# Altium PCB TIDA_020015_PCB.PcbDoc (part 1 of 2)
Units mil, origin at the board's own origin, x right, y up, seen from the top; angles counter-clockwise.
Board outline 1470 x 1510 mil, 2 copper layers (Top Layer, Bottom Layer), stack 62 mil thick; 90 components, 41 nets, 222 pads, 53 vias.
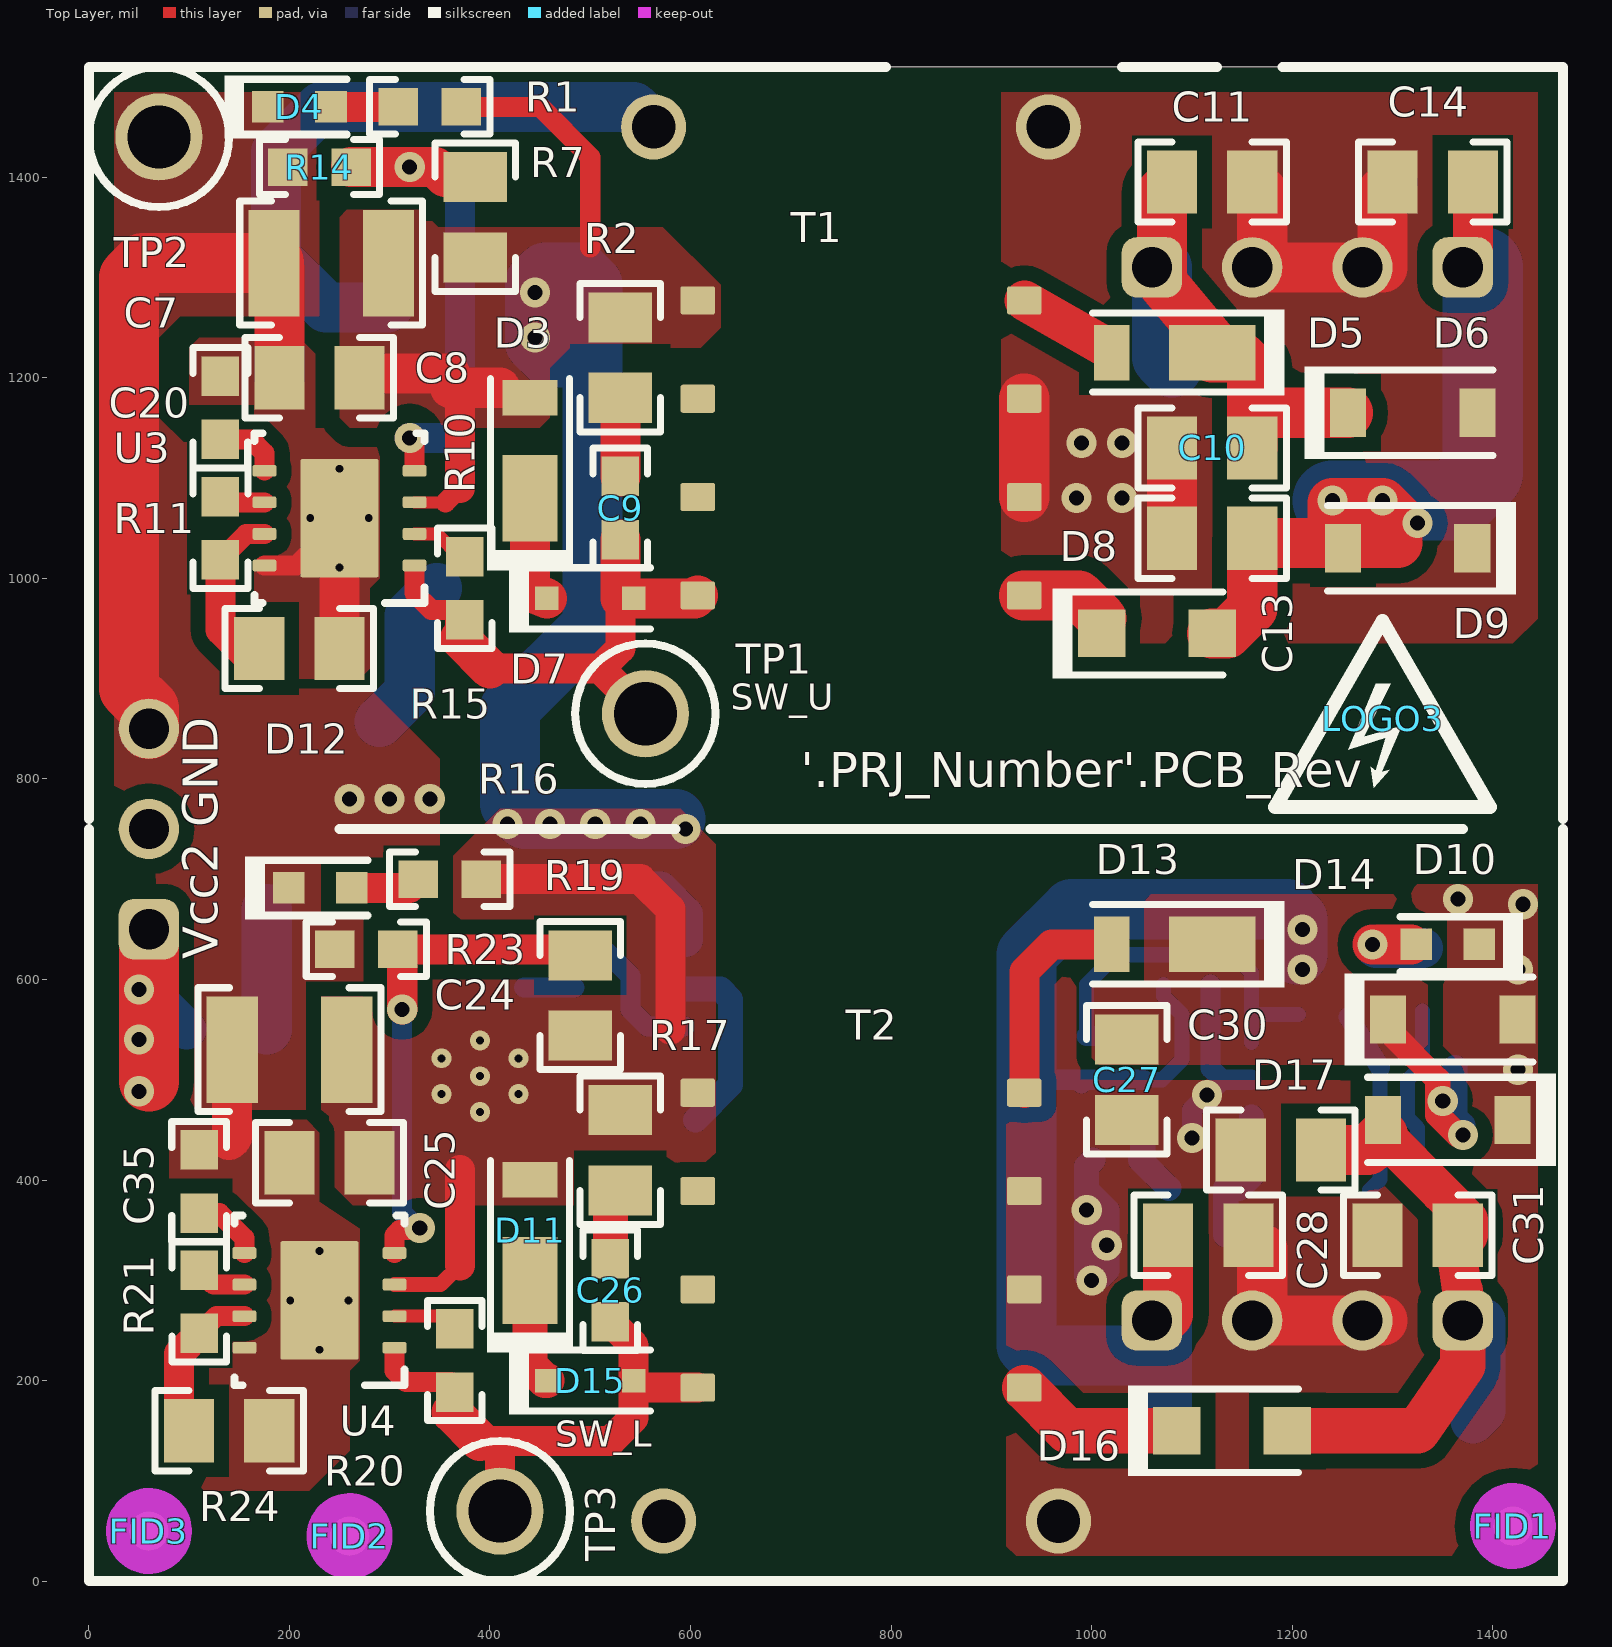
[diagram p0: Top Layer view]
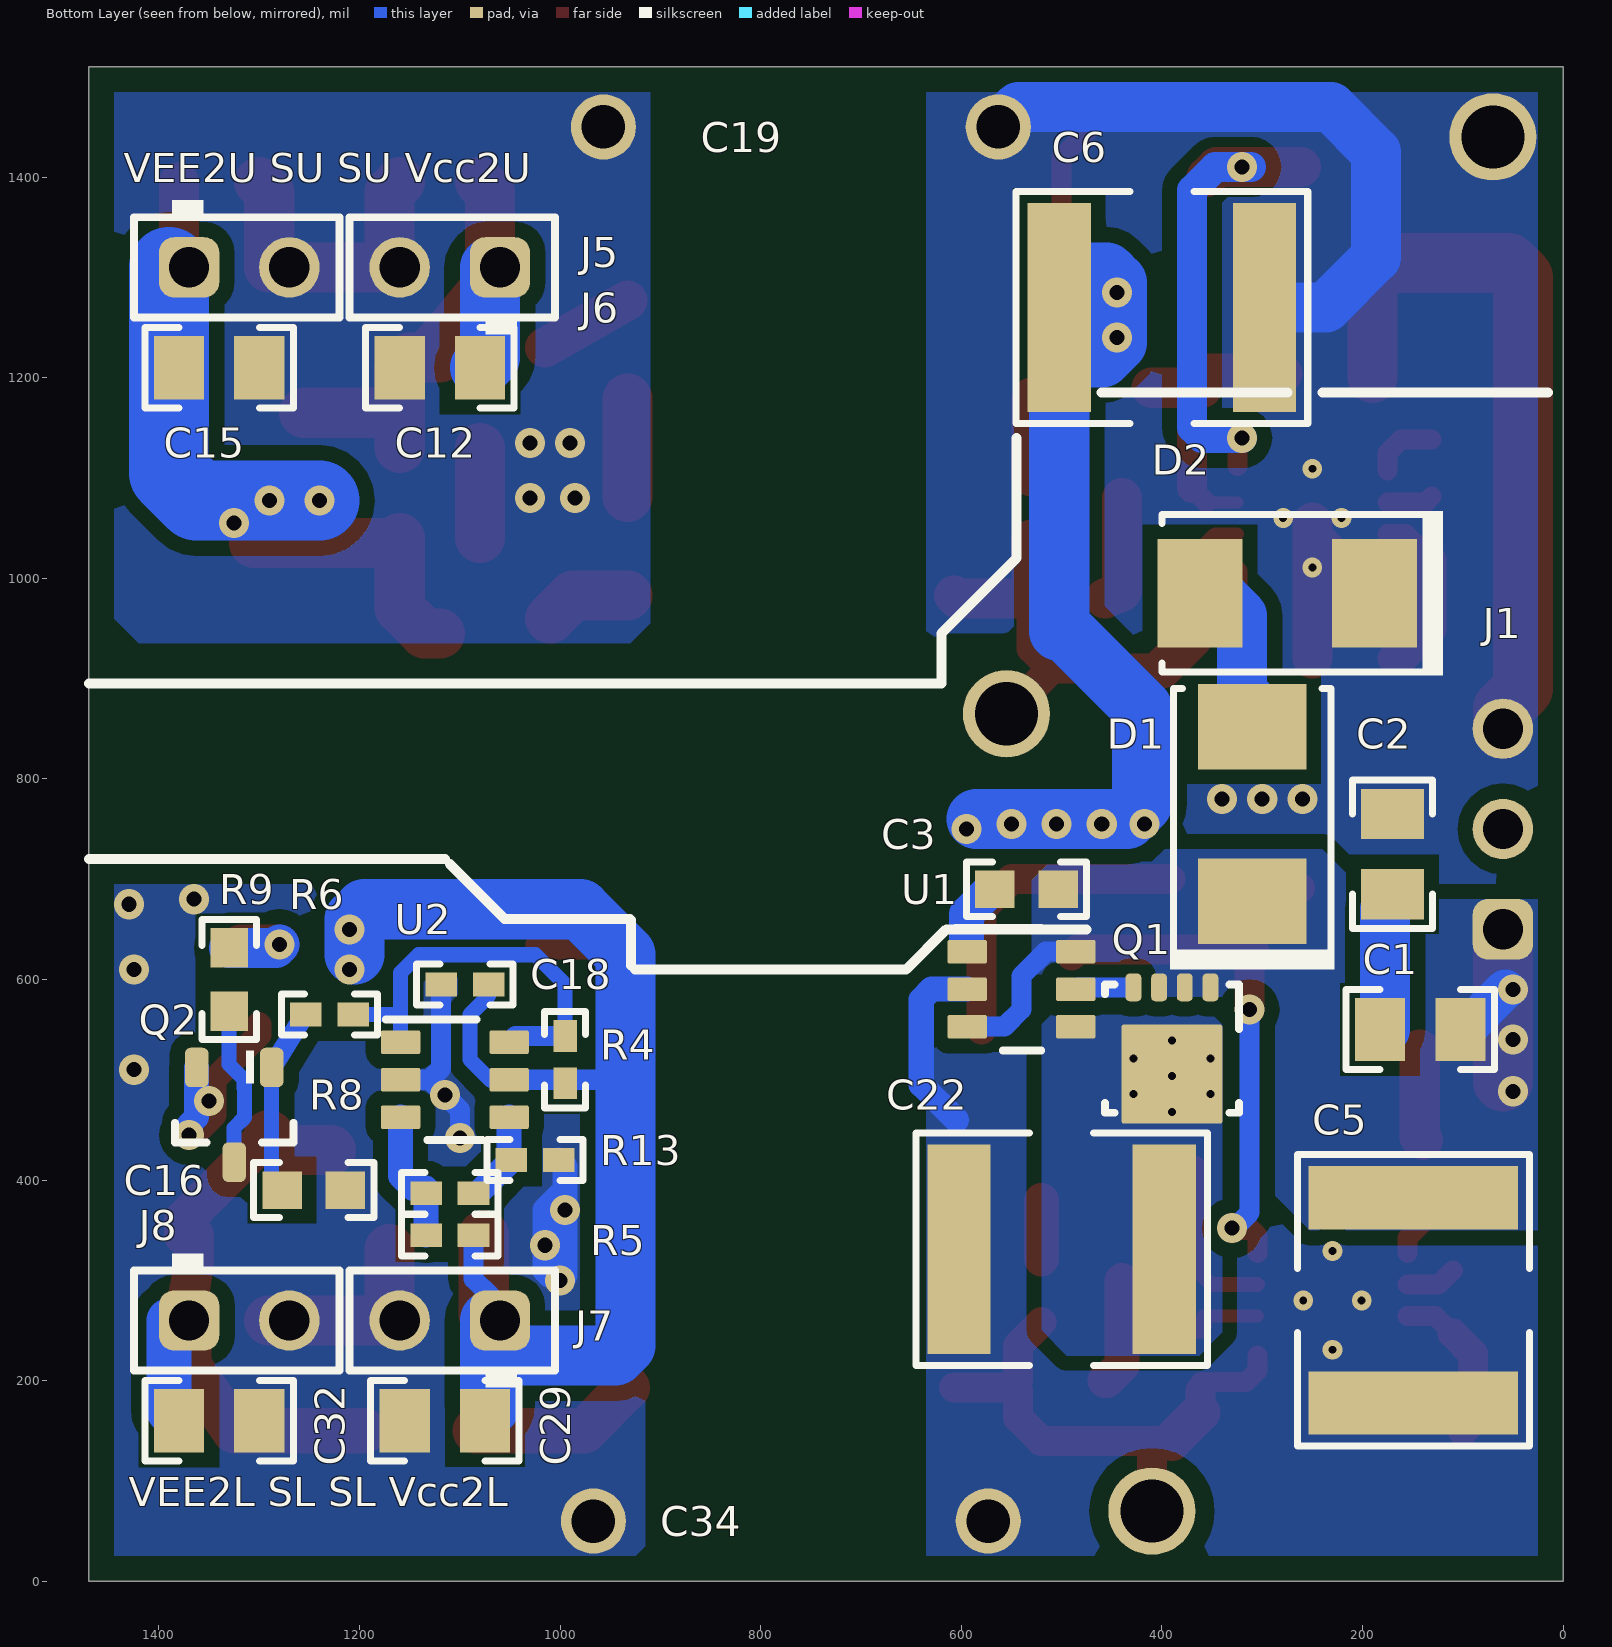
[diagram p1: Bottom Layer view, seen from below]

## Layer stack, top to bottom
Top Solder: solder mask 0.4, Solder Resist, Dk 3.5
Top Layer: signal copper 1.4
Dielectric1: core 59.2, FR-4, Dk 4.8
Bottom Layer: signal copper 1.4
Bottom Solder: solder mask 0.4, Solder Resist, Dk 3.5

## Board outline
0,0 1470,0 1470,1510 0,1510

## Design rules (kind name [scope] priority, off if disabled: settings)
AcuteAngle [All] p1: minimum=4.50000000000000E+0001 checktracksonly=FALSE
AssemblyTestPointUsage [All] p1: valid=2
BoardOutlineClearance BoardOutlineClearance_MountingHoles [OnCopper and InComponentClass('Mounting Holes')] p1: gap=40 ignorepadtopadclearanceinfootprint=FALSE
BoardOutlineClearance BoardOutlineClearance_Poly [OnCopper and IsPoly] p2: gap=25 ignorepadtopadclearanceinfootprint=FALSE
BoardOutlineClearance [OnCopper and Not InComponentClass('Logo') and not InComponentClass('FiducialMark') and not InRegion(1000,500,4000,800) and not InPoly] p3: gap=10 ignorepadtopadclearanceinfootprint=FALSE
Clearance Clearance_SW [InNet('SW_L')or InNet('SW_U')] p1: gap=19 ignorepadtopadclearanceinfootprint=FALSE
Clearance Clearance_Vin_U1 [InNet('Vin') or InNet('Vin_Pri') vs not InComponent('U1')  Xor  NetQ1_4] p2: gap=19 ignorepadtopadclearanceinfootprint=FALSE
Clearance Clearance_Keepouts [((IsTrack Or IsArc) And Not InPoly) And IsFree and IsKeepOut vs ((IsTrack Or IsArc) And Not InPoly) And IsFree and IsKeepOut] p3: gap=0 ignorepadtopadclearanceinfootprint=FALSE
Clearance Clearance_Poly [InPolygon] p4: gap=15 ignorepadtopadclearanceinfootprint=FALSE
Clearance Clearance_FiducialMark [IsKeepOut and InComponentClass('FiducialMark') vs IsPad and InComponentClass('FiducialMark')] p5: gap=0 ignorepadtopadclearanceinfootprint=FALSE
Clearance [All] p6: gap=7.87 ignorepadtopadclearanceinfootprint=FALSE except(0: Arc-Hole Track-Hole SMDPad-Hole THPad-Hole Via-Hole Fill-Hole Poly-Hole Region-Hole Text-Hole)
ComponentClearance ComponentClearance_MountingHoles_FiducialMarks [InComponentClass('Mounting Holes') vs InComponentClass('FiducialMark')] p1: gap=50 collisioncheckmode=3 verticalgap=10 showdistances=FALSE
ComponentClearance ComponentClearance_Shunt [InComponentClass('Header') vs InComponentClass('Shunt')] p2: gap=0 collisioncheckmode=3 verticalgap=0 showdistances=FALSE
ComponentClearance ComponentClearance_Logo [InComponentClass('Logo')] p3: gap=50 collisioncheckmode=3 verticalgap=10 showdistances=FALSE
ComponentClearance ComponentClearance_ScrewToNut [(HasFootprint('NY PMS 440 0025 PH')) vs (HasFootprint('Keystone_1902C'))] p4: gap=5 collisioncheckmode=3 verticalgap=10 showdistances=FALSE
ComponentClearance ComponentClearance_MountingHoles [InComponentClass('Mounting Holes')] p5: gap=250 collisioncheckmode=3 verticalgap=100000 showdistances=FALSE
ComponentClearance ComponentClearance_SmallPassives [HasFootprint('0201*') or HasFootprint('0402*') or HasFootprint('0508') or HasFootprint('0603*') or HasFootprint('0612') or HasFootprint('0805*') or HasFootprint('0815*') or HasFootprint('0830*') or HasFootprint('1206*') or HasFootprint('1210*') or HasFootprint('1808*') or HasFootprint('1812*') or HasFootprint('1825*') or HasFootprint('2010*') or HasFootprint('2220*') or HasFootprint('2225*') or HasFootprint('2512*') or HasFootprint('2728*') or HasFootprint('3518*') vs HasFootprint('0201*') or HasFootprint('0402*') or HasFootprint('0508') or HasFootprint('0603*') or HasFootprint('0612') or HasFootprint('0805*') or HasFootprint('0815*') or HasFootprint('0830*') or HasFootprint('1206*') or HasFootprint('1210*') or HasFootprint('1808*') or HasFootprint('1812*') or HasFootprint('1825*') or HasFootprint('2010*') or HasFootprint('2220*') or HasFootprint('2225*') or HasFootprint('2512*') or HasFootprint('2728*') or HasFootprint('3518*')] p6: gap=14.96 collisioncheckmode=3 verticalgap=10 showdistances=FALSE
ComponentClearance ComponentClearance_THtoSMT [IsThruComponent vs IsSMTComponent] p7: gap=20 collisioncheckmode=3 verticalgap=20 showdistances=FALSE
ComponentClearance ComponentClearance_THtoTH [IsThruComponent vs IsThruComponent] p8: gap=10 collisioncheckmode=3 verticalgap=20 showdistances=FALSE
ComponentClearance [All] p9: gap=20 collisioncheckmode=3 verticalgap=10 showdistances=FALSE
DiffPairsRouting [All] p1: maxlimit=100 minlimit=10 mostfreqgap=10 toplayer_minwidth=15 toplayer_maxwidth=15 toplayer_prefwidth=15 bottomlayer_minwidth=15 bottomlayer_maxwidth=15 bottomlayer_prefwidth=15 maxuncoupledlength=1000
FabricationTestPointUsage TestPointUsage [All] p1: valid=2 allowmultiple=FALSE
FabricationTestpoint Testpoint [All] p1: side=3 testpointundercomponent=TRUE minsize=40 maxsize=100 preferedsize=60 minholesize=0 maxholesize=40 preferedholesize=32 testpointgrid=1 allowsidetop=TRUE allowsidebottom=TRUE usegrid=TRUE gridtolerance=0.01
FanoutControl Fanout_LCC [IsLCC] p1: bgadir=Out bgaviamode=Centered fanoutstyle=Auto fanoutdirection=Alternating viagrid=1 // Fanout_LCC (Default Rule)
FanoutControl Fanout_BGA [IsBGA] p2: bgadir=Out bgaviamode=Centered fanoutstyle=Auto fanoutdirection=Alternating viagrid=1 // Fanout_BGA (Default Rule)
FanoutControl Fanout_Default [All] p4: bgadir=Out bgaviamode=Centered fanoutstyle=Auto fanoutdirection=Alternating viagrid=1 // Fanout_Default (Default Rule)
FanoutControl Fanout_Small [(CompPinCount < 5)] p5: bgadir=Out bgaviamode=Centered fanoutstyle=Auto fanoutdirection=OutThenIn viagrid=1 // Fanout_Small (Default Rule)
HoleSize [All] p1: absolutevalues=TRUE maxlimit=251 minlimit=7.87 maxpercent=80.000 minpercent=20.000
MinimumAnnularRing MinimumAnnularRing_ThermalPadVias [IsVia and InAnyComponent] p1: minimumring=5.91
MinimumAnnularRing [All] p2: minimumring=7
MinimumSolderMaskSliver MinimumSolderMaskSliver_Logo [InComponentClass('Logo') vs InComponentClass('Logo')] p1: minsoldermaskwidth=0.7
MinimumSolderMaskSliver [All] p2: minsoldermaskwidth=3.94
PlaneClearance [All] p1: clearance=15
PlaneConnect [All] p1: planeconnectstyle=Relief reliefexpansion=10 reliefentries=4 reliefconductorwidth=10 reliefairgap=10
PolygonConnect [All] p1: connectstyle=Direct reliefconductorwidth=10 reliefentries=4 polygonreliefangle="90 Angle" airgapwidth=10
RoutingVias ThermalPadVias [IsVia and InAnyComponent] p1: holewidth=7.87 width=19.68 viastyle="Through Hole" minholewidth=7.87 minwidth=19.68 maxholewidth=12.99 maxwidth=23.62
RoutingVias [All] p2: holewidth=16 width=34 viastyle="Through Hole" minholewidth=7.87 minwidth=26 maxholewidth=40 maxwidth=65
SilkToBoardRegionClearance [Not ((IsComment or IsDesignator) And (Hide <> 'False')) and not InRegion(1000,500,4000,800)] p1:
SilkToSilkClearance SilkToSilkClearance_Pb-FreeLogo [(HasFootprint('Pb-Free_Overlay_Medium') OR HasFootprint('Pb-Free_Overlay_Small')) vs (HasFootprint('Pb-Free_Overlay_Medium') OR HasFootprint('Pb-Free_Overlay_Small'))] p1: silktosilkclearance=0
SilkToSilkClearance [All] p2: silktosilkclearance=0
SilkToSolderMaskClearance SilkToComponentPadClearance [(IsPad or IsFill or IsRegion) and InAnycomponent] p1: minsilkscreentomaskgap=0 clearancetoexposedcopper=TRUE
SilkToSolderMaskClearance "Silk to Solder Mask Opening" [All] p2: minsilkscreentomaskgap=0 clearancetoexposedcopper=FALSE
SolderMaskExpansion [All] p1: expansion=1.97
Width [All] p1: maxlimit=100 minlimit=6 preferedwidth=10 checkconnectedcopper=TRUE
14 further rules are at their usual default settings.

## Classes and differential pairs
component class AssemblyNote: ZZ1 ZZ2 ZZ3
component class FiducialMark: FID1 FID2 FID3
component class TIDA_020015_PSR_Flyback_Hardware: FID1 FID2 FID3 LOGO3 ZZ1 ZZ2 ZZ3
component class Header: J1 J5 J6 J7 J8
component class TIDA-020015_PSR_Flyback: C1 C2 C3 C5 C6 C7 C8 C9 C10 C11 C12 C13 C14 C15 C16 C18 C19 C20 C22 C24 C25 C26 C27 C28 C29 C30 C31 C32 C34 C35 D1 D2 D3 D4 D5 D6 D7 D8 D9 D10 D11 D12 D13 D14 D15 D16 D17 J1 J5 J6 J7 J8 Q1 Q2 R1 R2 R4 R5 R6 R7 R8 R9 R10 R11 R13 R14 R15 R16 R17 R19 R20 R21 R23 R24 T1 T2 TP1 TP2 TP3 U1 U2 U3 U4

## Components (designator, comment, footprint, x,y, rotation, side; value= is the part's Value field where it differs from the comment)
C1 "GRM21BR71H104KA01L" 0805_HV 142.48,550 r0 bottom value=0.1uF
C2 "GRM21BR71H104KA01L" 0805_HV 170,725 r270 bottom value=0.1uF
C3 "GRM188R61H105KAALD" 0603 535,690 r180 bottom value=1uF
C5 "C5750X7S2A106K230KB" 2220_250 149.29,280 r270 bottom value=10uF
C6 "C5750X7S2A106K230KB" 2220_250 400,1270 r180 bottom value=10uF
C7 "GCM32DC72A475KE02L" 1210_220 241.73,1314.3 r180 top value=4.7uF
C8 "GRM21BR72A104KAC4L" 0805_HV 230,1200 r180 top value=0.1uF
C9 "GRM1885C2A221JA01D" 0603 530,1070 r270 top value=220pF
C10 "GRM21BR61E226ME44L" 0805_HV 1120,1130 r180 top value=22uF
C11 "GRM21BR61E226ME44L" 0805_HV 1120,1395 r0 top value=22uF
C12 "GRM21BR71H224KA01L" 0805_HV 1120,1210 r0 bottom value=0.22uF
C13 "GRM21BR61E226ME44L" 0805_HV 1120,1040 r0 top value=22uF
C14 "GRM21BR61E226ME44L" 0805_HV 1340,1395 r0 top value=22uF
C15 "GRM21BR71H224KA01L" 0805_HV 1340,1210 r0 bottom value=0.22uF
C16 "GRM1885C2A101JA01D" 0603 1245.66,390 r180 bottom value=100pF
C18 "Capacitor" 0402 1095,595 r0 bottom value=0.1uF
C19 "S102M59Z5UU83L0R" S102_1500x800x1800 760,1450 r180 bottom value=1000pF
C20 "GRM188R71C473KA01D" 0603 131.3,1170 r90 top value=0.047uF
C22 "C5750X7S2A106K230KB" 2220_250 500,331.02 r0 bottom value=10uF
C24 "GCM32DC72A475KE02L" 1210_220 200,530 r180 top value=4.7uF
C25 "GRM21BR72A104KAC4L" 0805_HV 240,417.24 r180 top value=0.1uF
C26 "GRM1885C2A221JA01D" 0603 520,290 r270 top value=220pF
C27 "GRM21BR61E226ME44L" 0805_HV 1035,500 r270 top value=22uF
C28 "GRM21BR61E226ME44L" 0805_HV 1116.22,345 r0 top value=22uF
C29 "GRM21BR71H224KA01L" 0805_HV 1115,160 r0 bottom value=0.22uF
C30 "GRM21BR61E226ME44L" 0805_HV 1188.66,430 r0 top value=22uF
C31 "GRM21BR61E226ME44L" 0805_HV 1325,345 r0 top value=22uF
C32 "GRM21BR71H224KA01L" 0805_HV 1340,160 r0 bottom value=0.22uF
C34 "S102M59Z5UU83L0R" S102_1500x800x1800 770,60 r180 bottom value=1000pF
C35 "GRM188R71C473KA01D" 0603 110,398.5 r90 top value=0.047uF
D1 "SMBJ26A-13-F" SMB 310,765 r90 bottom value=26V
D2 "SMBJ14A-13-F" SMB 275,985 r0 bottom value=14V
D3 "DFLZ24-7" PowerDI123 440,1130 r90 top value=24V
D4 "150060GS75000" WL-SMCW_GREEN 210,1470 r0 top value=Green
D5 "DFLU1200-7" PowerDI123 1070,1225 r180 top value=200V
D6 "BZT52C18-7-F" SOD-123 1320,1165 r0 top value=18V
D7 "CMDD4448" SOD-323 500,980 r0 top value=75V
D8 "PMEG10010ELRX" SOD-123W 1065,945 r0 top value=100V
D9 "BZT52C8V2-7-F" SOD-123 1315,1030 r180 top value=8.2V
D10 "150060SS75000" WL-SMCW_RED 1355,635 r180 top value="Super Red"
D11 "DFLZ24-7" PowerDI123 440,350 r90 top value=24V
D12 "150060GS75000" WL-SMCW_GREEN 230.75,691.32 r0 top value=Green
D13 "DFLU1200-7" PowerDI123 1070,635 r180 top value=200V
D14 "BZT52C18-7-F" SOD-123 1360,560 r0 top value=18V
D15 "CMDD4448" SOD-323 500,200 r0 top value=75V
D16 "PMEG10010ELRX" SOD-123W 1140,150 r0 top value=100V
D17 "BZT52C8V2-7-F" SOD-123 1355,460 r180 top value=8.2V
FID1 "Fiducial" Fiducial10-20 1420,55 r0 top
FID2 "Fiducial" Fiducial10-20 260,45 r0 top
FID3 "Fiducial" Fiducial10-20 60,50 r0 top
J1 "TSW-103-08-G-S" Samtec_TSW-103-08-x-S 60,750 r90 bottom
J5 "TSW-102-08-G-S" Samtec_TSW-102-08-x-S 1110,1310 r0 bottom
J6 "TSW-102-08-G-S" Samtec_TSW-102-08-x-S 1320,1310 r180 bottom
J7 "TSW-102-08-G-S" Samtec_TSW-102-08-x-S 1110,260 r0 bottom
J8 "TSW-102-08-G-S" Samtec_TSW-102-08-x-S 1320,260 r180 bottom
LOGO3 "DANGER HIGH VOLTAGE" IEC_HighVoltage_Small 1290,860 r0 top
Q1 "CSD18543Q3A" DNH0008A 390,531.02 r270 bottom value=60V
Q2 "BC857C-7-F" SOT-23 1325,465 r270 bottom value="45 V"
R1 "CRCW060310K0FKEA" 0603 340,1470 r0 top value=10.0k
R2 "CRCW0805100RFKEA" 0805_HV 530,1220 r90 top value=100
R4 "CRCW040249K9FKED" 0402 995,520 r90 bottom value=49.9k
R5 "CRCW0402240KFKED" 0402 1110,345 r180 bottom value=240k
R6 "CRCW040210K0FKED" 0402 1230,565 r0 bottom value=10.0k
R7 "CRCW0805100KFKEA" 0805_HV 385.4,1360 r270 top value=100k
R8 "CRCW04021K82FKED" 0402 1110,386.81 r0 bottom value=1.82k
R9 "CRCW060315K0FKEA" 0603 1330,600 r270 bottom value=15.0k
R10 "CRCW0603154KFKEA" 0603 375,990 r270 top value=154k
R11 "CRCW0603301KFKEA" 0603 131.3,1050 r270 top value=301k
R13 "CRCW04025K76FKED" 0402 1025,420 r0 bottom value=5.76k
R14 "CRCW0603976KFKEA" 0603 230,1410 r0 top value=976k
R15 "CRCW080512K1FKEA" 0805_HV 210,930 r180 top value=12.1k
R16 "CRCW060310K0FKEA" 0603 360,700 r0 top value=10.0k
R17 "CRCW0805100RFKEA" 0805_HV 530,429.7 r90 top value=100
R19 "CRCW0805100KFKEA" 0805_HV 490,584.01 r270 top value=100k
R20 "CRCW0603154KFKEA" 0603 365,220 r270 top value=154k
R21 "CRCW0603301KFKEA" 0603 110,278.5 r270 top value=301k
R23 "CRCW0603976KFKEA" 0603 276.81,630 r0 top value=976k
R24 "CRCW080512K1FKEA" 0805_HV 140,150 r180 top value=12.1k
T1 "YA8916-BL" Coilcraft_YA8916-BL 770,1130 r0 top value=30uH
T2 "YA8916-BL" Coilcraft_YA8916-BL 770,340 r0 top value=30uH
TP1 "5005" Keystone5005 555,865 r0 top
TP2 "5006" Keystone5006 70,1440 r0 top
TP3 "5005" Keystone5005 410,70 r0 top
U1 "LM74700QDBVTQ1" DBV0006A_N 540,590.3 r180 bottom
U2 "TPS3700QDDCRQ1" DDC0006A_N 1105,500 r180 bottom
U3 "LM5180QNGURQ1" NGU0008C 250,1060 r180 top
U4 "LM5180QNGURQ1" NGU0008C 230,280 r180 top
ZZ1 "These assemblies are ESD sensitive, ESD precautions shall be observed." AssemblyNote 185,3829.11 r0 top
ZZ2 "These assemblies must be clean and free from flux and all contaminants. Use of no clean flux is not acceptable." AssemblyNote 185,3740.56 r0 top
ZZ3 "These assemblies must comply with workmanship standards IPC-A-610 Class 2, unless otherwise specified." AssemblyNote 185,3652 r0 top

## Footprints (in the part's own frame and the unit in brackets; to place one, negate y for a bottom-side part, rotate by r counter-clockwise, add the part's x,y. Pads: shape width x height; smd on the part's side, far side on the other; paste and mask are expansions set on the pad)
0402 [mm] "0402 from SM-752 data"
  rect 0.8x0.6 smd: 1(-0.6,0) 2(0.6,0)
  silkscreen extent -1.22,-0.52 1.22,0.52, body extent -0.55,-0.3 0.55,0.3, height 0.6
0603 [mm] "0603 from SM-752 data"
  rect 1x0.95 smd: 1(-0.8,0) 2(0.8,0)
  silkscreen extent -1.52,-0.69 1.52,0.69, body extent -0.87,-0.47 0.87,0.47, height 1
0805_HV [mil] "0805 with 30mil clearance between pads"
  rect 50x63 smd: 1(-40,0) 2(40,0)
  silkscreen extent -74,-40 74,40, body extent -43,-29 43,29, height 57
1210_220 [mm] "1210"
  rect 1.3x2.7 smd: 1(-1.45,0) 2(1.45,0)
  silkscreen extent -2.32,-1.57 2.32,1.57, body extent -1.7,-1.35 1.7,1.35, height 2.2
2220_250 [mm] "2220"
  rect 1.6x5.3 smd: 1(-2.6,0) 2(2.6,0)
  silkscreen extent -3.69,-2.94 3.69,2.94, body extent -2.95,-2.62 2.95,2.62, height 2.5
AssemblyNote [mil] "Assembly Note"
Coilcraft_YA8916-BL [mm] "SMD, 8-Leads, Body 9.3x10.2mm, Pitch 2.49mm"
  rrect14% 0.87x0.71 smd: 1(-4.135,3.735) 2(-4.135,1.245) 3(-4.135,-1.245) 4(-4.135,-3.735) 5(4.135,-3.735) 6(4.135,-1.245) 7(4.135,1.245) 8(4.135,3.735)
  body extent -4.65,-5.1 4.65,5.1, height 10.6
DBV0006A_N [mm] "SOT23, 6-Leads, Body 2.9x1.6mm, Pitch 0.95mm, Lead Span 2.8mm, IPC Medium Density"
  rrect17% 1x0.6 smd: 1(-1.375,0.95) 2(-1.375,0) 3(-1.375,-0.95) 4(1.375,-0.95) 5(1.375,0) 6(1.375,0.95)
  silkscreen extent -1.68,-1.55 0.5,1.55, body extent -1.42,-1.46 1.42,1.46, height 1.12
DDC0006A_N [mm]
  rrect17% 1x0.6 smd: 1(-1.375,0.95) 2(-1.375,0) 3(-1.375,-0.95) 4(1.375,-0.95) 5(1.375,0) 6(1.375,0.95)
  silkscreen extent -1.75,-1.52 0.7,1.53, body extent -1.43,-1.48 1.43,1.49, height 0.92
DNH0008A [mm] "8 pin VSONP, 0.65 mm pitch"
  rrect50% 0.7x0.4 smd paste-0.05 mask-0.05: 1(-1.55,0.975) 2(-1.55,0.325) 3(-1.55,-0.325) 4(-1.55,-0.975) 5(1.55,-0.975) 6(1.55,-0.325) 7(1.55,0.325) 8(1.55,0.975)
  rrect14% 0.705x1.125 on Bottom Paste: 9(-0.208,-0.663) 9(-0.208,0.662) 9(0.697,-0.663) 9(0.697,0.662)
  rrect6% 1.775x2.45 on Bottom Solder: 9(0.327,0)
  rrect4% 2.51x2.55 smd paste-1.5 mask-1.5: 9(0.645,0)
  rect 0.5x0.3 on Bottom Solder: 9(1.175,-0.975) 9(1.175,-0.325) 9(1.175,0.325) 9(1.175,0.975)
  silkscreen extent -1.62,-1.7 1.62,1.7, body extent -1.65,-1.65 1.65,1.66, height 0.91
Fiducial10-20 [mm]
  round 1 smd mask+0.5: 1(0,0)
  Top Layer keep-out circle w1.178: c0,0 r0.5
IEC_HighVoltage_Small [mil]
  silkscreen extent -107,-88 107,97
Keystone5005 [mil] "Keystone Compact loops"
  round 87 hole 63: 1(0,0)
  silkscreen extent -70,-70 70,70, body extent -63,-63 62,63, height 225
Keystone5006 [mil] "Keystone Compact loops"
  round 87 hole 63: 1(0,0)
  silkscreen extent -70,-70 70,70, body extent -63,-63 62,63, height 225
NGU0008C [mm] "SON, 8-Leads, Body 4x4mm, Pitch 0.8mm"
  rrect33% 0.6x0.3 smd: 1(-1.9,1.2) 2(-1.9,0.4) 3(-1.9,-0.4) 4(-1.9,-1.2) 5(1.9,-1.2) 6(1.9,-0.4) 7(1.9,0.4) 8(1.9,1.2)
  rrect8% 1.75x1.31 on Top Paste: 9(0,0.755) 9(0,-0.755)
  rrect5% 1.98x3 smd paste-1.5: 9(0,0)
  silkscreen extent -2.15,-2.15 2.15,2.15, body extent -2,-2 2,2, height 0.77
PowerDI123 [mm] "Diodes Inc recommended land pattern, document number DS30628 Rev. 6-2"
  rect 2.2x1.4 smd: 1(-1.275,0)
  rect 0.9x1.4 smd: 2(1.275,0)
  silkscreen extent -3.1,-1.09 1.76,1.09, body extent -2.38,-0.97 1.52,0.96, height 1
S102_1500x800x1800 [mm] "TH, 2-Leads, Body 15x8mm, Pin Spacing 10mm"
  round 1.65 hole 1.1: 1(-5,0) 2(5,0)
  body extent -7.5,-4 7.5,4, height 21.83
Samtec_TSW-102-08-x-S [mm] "Header, 2.54mm, 2x1, TH"
  rrect50% 1.53x1.53 hole 1.02: 1(-1.27,0)
  round 1.53 hole 1.02: 2(1.27,0)
  silkscreen extent -2.67,-1.27 2.54,1.7, body extent -2.67,-1.27 2.54,1.27, height 8.38
Samtec_TSW-103-08-x-S [mm] "Header, 2.54mm, 3x1, TH"
  rrect50% 1.53x1.53 hole 1.02: 1(-2.54,0)
  round 1.53 hole 1.02: 2(0,0) 3(2.54,0)
  body extent -3.94,-1.27 3.81,1.27, height 8.38
SMB [mil] "Molded Diode, 2-Leads, Body 5.4x3.6mm, IPC Medium Density, based on OnSemi component dimensions"
  rect 85x107.99 smd: 1(-87.01,0) 2(87.01,0)
  silkscreen extent -155,-82 125,82, body extent -106,-71 106,71, height 91
SOD-123 [mm] "On Semi recommended land pattern"
  rect 0.915x1.22 smd: 1(-1.637,0) 2(1.637,0)
  silkscreen extent -2.74,-1.17 2.03,1.17, body extent -1.93,-0.9 1.93,0.9, height 1.35
SOD-123W [mm] "NXP recommended land pattern"
  rect 1.2x1.2 smd paste-0.05: 1(-1.4,0) 2(1.4,0)
  silkscreen extent -2.64,-1.14 1.68,1.14, body extent -1.85,-0.95 1.85,0.95, height 1.1
SOD-323 [mm] "NXP recommended land pattern"
  rect 0.6x0.6 smd paste-0.05: 1(-1.1,0) 2(1.1,0)
  silkscreen extent -2.06,-0.86 1.53,0.86, body extent -1.3,-0.67 1.3,0.68, height 1.1
SOT-23 [mm] "SOT23, 3-Leads, Body 2.9x1.3mm, Pitch 0.95mm, Lead Span 2.5mm, IPC Medium Density"
  rrect50% 1x0.6 smd: 1(-1.2,0.95) 2(-1.2,-0.95) 3(1.2,0)
  silkscreen extent -1.63,-1.5 0.7,1.5, body extent -1.16,-1.45 1.21,1.45, height 1
WL-SMCW_GREEN [mm] "WURTH"
  rect 0.8x0.8 smd: 1(-0.8,0) 2(0.8,0)
  silkscreen extent -1.9,-0.8 1.2,0.8, body extent -0.85,-0.45 0.85,0.45, height 0.8
WL-SMCW_RED [mm] "WURTH"
  rect 0.8x0.8 smd: 1(-0.8,0) 2(0.8,0)
  silkscreen extent -1.9,-0.8 1.2,0.8, body extent -0.85,-0.45 0.85,0.45, height 0.8

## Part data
C1 C2: "CAP, CERM, 0.1 μF, 50 V,+/- 10%, X7R, 0805", Cap_Case=0805, Manufacturer=MuRata, Supplier Part Number 1=490-1666-1-ND, TempCo=X7R, Tolerance_%=10, Value2=50V, ValueDisplayed=0.1μF
C3: "CAP, CERM, 1 μF, 50 V,+/- 10%, X5R, 0603", Cap_Case=0603, Manufacturer=MuRata, Supplier Part Number 1=13T1194, TempCo=X5R, Tolerance_%=10, Value2=50V, ValueDisplayed=1μF
C5 C6 C22: "CAP, CERM, 10 μF, 100 V,+/- 10%, X7S, 2220", Cap_Case=2220, Manufacturer=TDK, Supplier Part Number 1=445-13408-1-ND, TempCo=X7S, Tolerance_%=10, Value1="0.003179 ohm", Value2=100V, ValueDisplayed=10μF
C7 C24: library part CMP-0082268-1, "CAP, CERM, 4.7 μF, 100 V,+/- 10%, X7S, AEC-Q200 Grade 1, 1210", Cap_Case=1210, Manufacturer=MuRata, Supplier Part Number 1=490-14484-1-ND, TempCo=X7S, Tolerance_%=10%, Value1="0.001 ohm", Value2=100V, ValueDisplayed=4.7μF
C8 C25: "CAP, CERM, 0.1 μF, 100 V,+/- 10%, X7R, 0805", Cap_Case=0805, Manufacturer=MuRata, Supplier Part Number 1=490-12005-1-ND, TempCo=X7R, Tolerance_%=10, Value2=100V, ValueDisplayed=0.1μF
C9 C26: "CAP, CERM, 220 pF, 100 V,+/- 5%, C0G/NP0, 0603", Cap_Case=0603, Manufacturer=MuRata, Supplier Part Number 1=490-1359-1-ND, TempCo=C0G/NP0, Tolerance_%=5, Value2=100V, ValueDisplayed=220pF
C10 C11 C13 C14 C27 C28 C30 C31: "CAP, CERM, 22 μF, 25 V,+/- 20%, X5R, 0805", Cap_Case=0805, Manufacturer=MuRata, Supplier Part Number 1=490-10749-1-ND, TempCo=X5R, Tolerance_%=20, Value2=25V, ValueDisplayed=22μF
C12 C15 C29 C32: "CAP, CERM, 0.22 μF, 50 V,+/- 10%, X7R, 0805", Cap_Case=0805, Manufacturer=MuRata, Supplier Part Number 1=490-1670-1-ND, TempCo=X7R, Tolerance_%=10, Value2=50V, ValueDisplayed=0.22μF
C16: "CAP, CERM, 100 pF, 100 V,+/- 5%, C0G/NP0, 0603", Cap_Case=0603, Manufacturer=MuRata, Supplier Part Number 1=490-1351-1-ND, TempCo=C0G/NP0, Tolerance_%=5, Value2=100V, ValueDisplayed=100pF
C18: library part CMP-0006562-2, "CAP, CERM, 0.1 uF, 10 V, +/- 10%, X5R, 0402", Cap_Case=0402, Manufacturer=MuRata, PartNumber=GRM155R61A104KA01D, Supplier Part Number 1=490-1318-1-ND, TempCo=X5R, Tolerance_%=10%, Value1=Unknown, Value2=10V, ValueDisplayed=0.1uF
C19 C34: library part CMP-0084156-1, "CAP, CERM, 1000 pF, 6000 V,+/- 20%, Z5U, 15x8mm", Cap_Case=15x8x18, Manufacturer=Vishay-Bccomponents, TempCo=Z5U, Tolerance_%=20%, Value2=6000V, ValueDisplayed=1000pF
C20 C35: "CAP, CERM, 0.047 μF, 16 V,+/- 10%, X7R, 0603", Cap_Case=0603, Manufacturer=MuRata, Supplier Part Number 1=490-1529-1-ND, TempCo=X7R, Tolerance_%=10, Value2=16V, ValueDisplayed=0.047μF
D1: library part CMP-0005559-2, "Diode, TVS, Uni, 26 V, 42.1 Vc, SMB", Manufacturer="Diodes Inc.", Power_W=5W, Supplier Part Number 1=SMBJ26A-FDICT-ND
D2: library part CMP-0005543-2, "Diode, TVS, Uni, 14 V, 23.2 Vc, SMB", Manufacturer="Diodes Inc.", Power_W=5W, Supplier Part Number 1=SMBJ14A-FDICT-ND
D3 D11: library part CMP-0005415-2, "Diode, Zener, 24 V, 1 W, PowerDI123", Manufacturer="Diodes Inc.", Power_W=1W, Supplier Part Number 1=DFLZ24DICT-ND
D4 D12: library part CMP-0002905-1, "LED, Green, SMD", Color=Green, Manufacturer="Wurth Elektronik", Supplier Part Number 1=732-4971-1-ND, Value1=W, Value2=3.2V
D5 D13: library part CMP-0077072-1, "Diode, Superfast Rectifier, 200 V, 1 A, AEC-Q101, PowerDI123", Manufacturer="Diodes Inc.", Supplier Part Number 1=DFLU1200-7DICT-ND, Value1=1A, Value2=0.98V
D6 D14: library part CMP-0084402-1, "Diode, Zener, 18 V, 500 mW, AEC-Q101, SOD-123", Manufacturer="Diodes Inc.", Power_W=500mW, Value1=0.5W
D7 D15: library part CMP-0029019-1, "Diode, Ultrafast, 75 V, 0.25 A, SOD-323", Manufacturer="Central Semiconductor", Value1=0.25A, Value2=1.2V
D8 D16: library part CMP-0028782-1, "Diode, Schottky, 100 V, 1 A, AEC-Q101, SOD-123W", Manufacturer=Nexperia, Supplier Part Number 1=568-12693-1-ND, Value1=1A, Value2=0.77V
D9 D17: library part CMP-0005813-1, "Diode, Zener, 8.2 V, 500 mW, SOD-123", Manufacturer="Diodes Inc.", Power_W=500mW, Supplier Part Number 1=BZT52C8V2-FDICT-ND, Value1=0.5W
D10: "LED, Super Red, SMD", Color="super red", Manufacturer="Wurth Elektronik", Supplier Part Number 1=732-4979-1-ND, Value1=W, Value2=1.9V
FID1 FID2 FID3: library part CMP-0077181-1, "Fiducial mark.  There is nothing to buy or mount.", Manufacturer=N/A
J1: library part CMP-0079327-1, "Header, 2.54mm, 3x1, Gold, TH", Color=Black, Manufacturer=Samtec, Supplier Part Number 1=SAM1038-03-ND
J5 J6 J7 J8: library part CMP-0077643-1, "Header, 2.54mm, 2x1, Gold, TH", Color=Black, Current_A=5.7A, Manufacturer=Samtec, Supplier Part Number 1=SAM1038-02-ND, Voltage_V=550V
LOGO3: library part IEC_HighVoltage, "IEC 61010-1 High Voltage Warning"
Q1: "MOSFET, N-CH, 60 V, 35 A, DNH0008A (VSONP-8)", Alternate Manufacturer=None, Manufacturer="Texas Instruments", Supplier Part Number 1=CSD18543Q3A-ND, Value1="0.012 ohm", Value2="11.1 nC"
Q2: library part "BC857C-7-F, Diodes Inc.", "Transistor, PNP, 45 V, 0.1 A, SOT-23", Manufacturer="Diodes Inc.", Supplier Part Number 1=BC857C-FDICT-ND, Value1="0.1 A", Value2=600
R1 R16: "RES, 10.0 k, 1%, 0.1 W, 0603", Manufacturer=Vishay-Dale, Power_W=0.1, Supplier Part Number 1=541-10.0KHCT-ND, TempCo="100 ppm/C", Tolerance_%=1, Value1=1%, Value2=0.1W, Value_Code=10k0, ValueDisplayed=10.0k
R2 R17: "RES, 100, 1%, 0.125 W, 0805", Manufacturer=Vishay-Dale, Power_W=0.125, Supplier Part Number 1=541-100CCT-ND, TempCo="100 ppm/C", Tolerance_%=1, Value1=1%, Value2=0.125W, Value_Code=100R, ValueDisplayed=100
R4: library part CMP-0026403-1, "RES, 49.9 k, 1%, 0.063 W, 0402", Manufacturer=Vishay-Dale, Power_W=63mW, Supplier Part Number 1=541-49.9KLCT-ND, TempCo="100 ppm/C", Tolerance_%=1%, Value2=0.063W, Value_Code=49k9, ValueDisplayed=49.9k
R5: "RES, 240 k, 1%, 0.063 W, 0402", Manufacturer=Vishay-Dale, Power_W=0.063, Supplier Part Number 1=541-240KLCT-ND, TempCo="100 ppm/C", Tolerance_%=1, Value1=1%, Value2=0.063W, Value_Code=240k
R6: "RES, 10.0 k, 1%, 0.063 W, 0402", Manufacturer=Vishay-Dale, Power_W=0.063, Supplier Part Number 1=541-10.0KLCT-ND, TempCo="100 ppm/C", Tolerance_%=1, Value1=1%, Value2=0.063W, Value_Code=10k0, ValueDisplayed=10.0k
R7 R19: "RES, 100 k, 1%, 0.125 W, 0805", Manufacturer=Vishay-Dale, Power_W=0.125, Supplier Part Number 1=541-100KCCT-ND, TempCo="100 ppm/C", Tolerance_%=1, Value1=1%, Value2=0.125W, Value_Code=100k
R8: "RES, 1.82 k, 1%, 0.063 W, 0402", Manufacturer=Vishay-Dale, Power_W=0.063, Supplier Part Number 1=541-1.82KLCT-ND, TempCo="100 ppm/C", Tolerance_%=1, Value1=1%, Value2=0.063W, Value_Code=1k82, ValueDisplayed=1.82k
R9: "RES, 15.0 k, 1%, 0.1 W, 0603", Manufacturer=Vishay-Dale, Power_W=0.1, Supplier Part Number 1=541-15.0KHCT-ND, TempCo="100 ppm/C", Tolerance_%=1, Value1=1%, Value2=0.1W, Value_Code=15k0, ValueDisplayed=15.0k
R10 R20: "RES, 154 k, 1%, 0.1 W, 0603", Manufacturer=Vishay-Dale, Power_W=0.1, Supplier Part Number 1=541-154KHCT-ND, TempCo="100 ppm/C", Tolerance_%=1, Value1=1%, Value2=0.1W, Value_Code=154k
R11 R21: "RES, 301 k, 1%, 0.1 W, 0603", Manufacturer=Vishay-Dale, Power_W=0.1, Supplier Part Number 1=541-301KHCT-ND, TempCo="100 ppm/C", Tolerance_%=1, Value1=1%, Value2=0.1W, Value_Code=301k
R13: "RES, 5.76 k, 1%, 0.063 W, 0402", Manufacturer=Vishay-Dale, Power_W=0.063, Supplier Part Number 1=541-5.76KLCT-ND, TempCo="100 ppm/C", Tolerance_%=1, Value1=1%, Value2=0.063W, Value_Code=5k76, ValueDisplayed=5.76k
R14 R23: "RES, 976 k, 1%, 0.1 W, 0603", Manufacturer=Vishay-Dale, Power_W=0.1, Supplier Part Number 1=541-976KHCT-ND, TempCo="100 ppm/C", Tolerance_%=1, Value1=1%, Value2=0.1W, Value_Code=976k
R15 R24: "RES, 12.1 k, 1%, 0.125 W, 0805", Manufacturer=Vishay-Dale, Power_W=0.125, Supplier Part Number 1=541-12.1KCCT-ND, TempCo="100 ppm/C", Tolerance_%=1, Value1=1%, Value2=0.125W, Value_Code=12k1, ValueDisplayed=12.1k
T1 T2: library part CMP-0083973-1, "Transformer, 30 uH, SMT", Manufacturer=Coilcraft, ValueDisplayed=30μH
TP1 TP3: library part CMP-0055142-1, "Test Point, Compact, Red, TH", Color=Red, Manufacturer=Keystone, Supplier Part Number 1=36-5005-ND
TP2: library part CMP-0055143-1, "Test Point, Compact, Black, TH", Color=Black, Manufacturer=Keystone, Supplier Part Number 1=36-5006-ND
U1: library part CMP-0079180-1, "Low Iq Always ON Smart Diode Controller, DBV0006A (SOT-23-6)", Alternate Manufacturer="Texas Instruments", Alternate PartNumber=LM74700QDBVRQ1
U2: library part CMP-0067337-2, "Automotive, High-Voltage (18V) Window Comparator with Over- and Undervoltage Detection, DDC0006A (SOT-23-T-6)", Alternate Manufacturer="Texas Instruments"
U3 U4: library part CMP-0078633-2, "70-V PSR Flyback Converter With 100-V, 1.2-A Power Switch and Ultra-Low IQ, NGU0008C (WSON-8)", Alternate Manufacturer="Texas Instruments", Alternate PartNumber=LM5180QNGUTQ1
ZZ1: library part CMP-0077236-1
ZZ2: library part CMP-0077237-1
ZZ3: library part CMP-0077238-1

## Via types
v1: diameter 30, hole 15, Top Layer to Bottom Layer, 38 vias
v2: diameter 19.68, hole 7.87, Top Layer to Bottom Layer, 15 vias

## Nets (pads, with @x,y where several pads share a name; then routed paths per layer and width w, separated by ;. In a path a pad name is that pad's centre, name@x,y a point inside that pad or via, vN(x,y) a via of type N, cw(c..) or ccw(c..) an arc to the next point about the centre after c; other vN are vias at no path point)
+15V_Iso_L: C18.1 C27.1 C28.1 C29.1 D13.1 D14.1 J7.1 Q2.2 R4.1 R5.2 U2.5 | length 1562.3
  Top Layer w25: D14.1@1300.53,555 1300.53,544.47 1345,500 1345,465 v1@1365,445
  Top Layer w50: J7.1@1070,260 1076.22,266.22 C28.1@1076.22,345
  Bottom Layer w15: U2.5@1050.87,500 1070,500 1090,520 1090,565 1071.38,583.62 C18.1@1071.38,595
  Bottom Layer w20: 935,495 936.38,496.38 ; 940,500 R4.1@993.62,500 ; R4.1@990,496.38 R4.1@993.62,500 ; U2.5@1050.87,500 R4.1@993.62,500 ; J7.1@1070,260 1070,285 1086.38,301.38 R5.2@1086.38,345
  Bottom Layer w25: Q2.2@1362.4,512.24 1362.4,462.6 1370,455 v1(1370,445)
  Bottom Layer w60: C29.1@1070,175 1070,225 ; J7.1@1070,260 1070,225 ; 1195,670 980,670 935,625 935,495 935,235 945,225 1070,225 ; 1205,625 v1@1205,660
  other v1: 1350,479 1210,610 1210,650
+15V_Iso_U: C10.1 C11.1 C12.1 D5.1 D6.1 J5.1 | length 516
  Top Layer w50: C11.1@1080,1395 1070,1385 1070,1295 D5.1@1120,1235 ; D5.1@1120.2,1220 D5.1@1126.89,1220 ; D5.1@1125,1230 1125.75,1226.05 1126.66,1221.22 D5.1@1126.89,1220 ; C10.1@1160,1130 1160,1165 ; D6.1@1255.53,1165 1160,1165 ; D5.1@1126.89,1220 1150,1220 1160,1210 1160,1165
  Bottom Layer w60: J5.1@1070,1310 1070,1220 C12.1@1080,1210
-8V_Iso_L: C30.2 C31.2 C32.2 D16.2 D17.2 J8.1 | length 656.7
  Top Layer w40: D17.2@1290.53,445 1290.92,445 1347.87,388.05 1347.87,387.66 1375,360.53 C31.2@1375,345 ; C31.2@1365,345 1365,320 J8.1@1370,285 ; J8.1@1370,254.99 J8.1@1370,290
  Top Layer w45: D16.2@1195.12,150 1325,150 1370,215 J8.1@1370,260
  Top Layer w50: C30.2@1228.66,430 1275.53,430 D17.2@1290.53,445
  Bottom Layer w45: C32.2@1380,160 1390,170 J8.1@1390,260
-8V_Iso_U: C13.2 C14.2 C15.2 D8.2 D9.2 J6.1 | length 852
  Top Layer w40: J6.1@1370,1310 1380,1320 C14.2@1380,1395
  Top Layer w50: D8.2@1120.12,945 1135,945 1160,970 C13.2@1160,1040 ; C13.2@1165,1035 D9.2@1240,1035 ; D9.2@1240,1035 1240,1075 1290,1075 1305,1060 1305,1035 D9.2@1240,1035
  Bottom Layer w80: v1(1240,1077.5) v1(1290,1077.5) 1362.5,1077.5 1390,1105 J6.1@1390,1310
  other v1: 1325,1055
EN_L: R19.1 R23.2 U4.4 | length 518.1
  Top Layer w20: U4.4@304.8,327.24 304.8,344.8 310,350 v1@330,350
  Top Layer w30: v1(312.52,570) 312.52,625.79 R23.2@308.31,630 484.01,630 R19.1@490,624.01
  Bottom Layer w20: v1(312.52,570) 312.52,367.48 v1@330,350
  other v1: 330,352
